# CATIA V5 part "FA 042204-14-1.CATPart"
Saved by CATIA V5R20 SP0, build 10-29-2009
Part number: FA 042204-14-1
Revision: ANY
Definition: UNKNOWN
Nomenclature: FA 042204-14-1
Source: Unknown
Bounding box of the stored display mesh (mm): x -2 to 2, y 0.1 to 12.1, z -2 to 2
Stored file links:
  C:\Users\Utente\Desktop\IO LAVORO\3D X SITO CF\CUMSA\3D files FA\FA 042204-21\FA 042204-14-1.CATPart

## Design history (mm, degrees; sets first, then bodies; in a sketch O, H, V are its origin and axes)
Body1 "Cortar-Extruir3" (main body)
  Solid1: solid without history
